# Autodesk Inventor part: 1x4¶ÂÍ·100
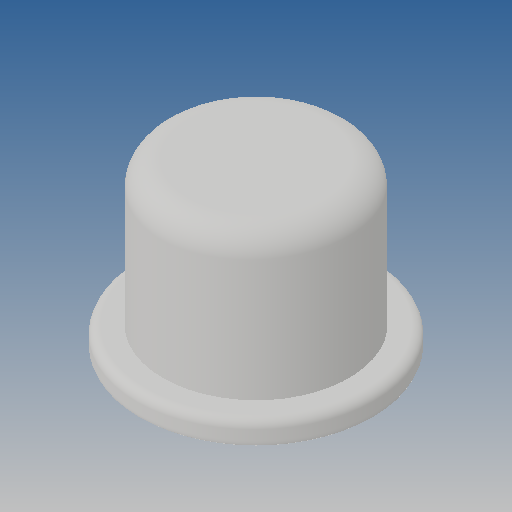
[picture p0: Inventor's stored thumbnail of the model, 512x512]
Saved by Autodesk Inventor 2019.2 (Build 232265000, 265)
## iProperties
Created: 2013-07
Part Number: 1x4¶ÂÍ·100
Material: Ogólny
Document SubType Name: Modeling
Designer: CADENGINEERING4
Density: 1 g/cm^3
Appearance: Domyślna
Author: CADENGINEERING4
Revision Number: ÈÎºÎ
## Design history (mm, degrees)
feature "Ô²½Ç1"
node "Bryła1"
